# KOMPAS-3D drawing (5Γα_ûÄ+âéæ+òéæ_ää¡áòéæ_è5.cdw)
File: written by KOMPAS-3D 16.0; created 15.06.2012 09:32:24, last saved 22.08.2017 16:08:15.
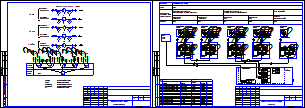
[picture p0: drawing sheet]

Sheets 1-2: A3, landscape

Title block, sheet 1: name: г. Москва, ул. Нежинская, д. 14, к.8 (кв. 1 и кв. 2); sheet number: 1; sheets: 27 / 28; sheet format: A3; stored path: D:\Проекты\Лыткарино\ул. Квартал 3А, д.25\710.74 РП.cdw; cell 320: Р
Title block, sheet 2: sheet number: 2

Views: Вид 2, Вид 3, Вид 4, Вид 5
Referenced files in C:\Program Files (x86)\ASCON\KOMPAS-3D V16\Sys\: SPDS.lcs, EngSys.lcs, GRAPHIC.LHS
Referenced files: graphic.tdp
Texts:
  МО, Клинский район, д. Решетниково, ул. Центральная, д.14
  GOST Common
  Normal
  List Paragraph
  heading 3
  для схемы
  txt
  краны
  Фоновая заливка
  Т0-элементы
  Агрегат
  Системный блок  МКТС
  Среда
  Вода
  параметра и место
  отбора импульса
  Учет тепловой энергии и
  теплоносителя системы отопления
  Подающий
  трубопровод
  отопления
  Обратный
  расхода горячей водысистемы ГВС
  Вводной
  трубопровод ХВС
  Узел учета ХВС
  ГВС
  ИМ1
  ИМ2
  ИМ3
  ИМ4
  ИМ5
  ВРУ
  Плата подключений
  СБ МКТС
  Pt 100
  Преобразователь
  температуры
  давления
  Измерительный
  модуль М121
  UP+
  UP-
  ИМП
  Лин
  каб.
  Начало
  трассы
  Трассы
  Марка
  Проложен
  Датчик температуры (Т1)
  Датчик температуры (Т2)
  Датчик температуры (Т3)
  Датчик температуры (Т4)
  Датчик давления (Т1)
  Датчик давления (Т2)
  Датчик давления (Т3)
  Датчик давления (В1)
  Датчик давления (Т4)
  Изм. модуль (Т1)
  Изм. модуль (Т2)
  Изм. модуль (Т3)
  Изм. модуль (Т4)
  Изм. модуль (В1)
  ВРУ 220В, 50 Гц
  ИМ1 УУТЭ
  ИМ2 УУТЭ
  ИМ2 УУГВС
  ИМ1 УУХВС
  ИМ (Т1)
  ИМ (Т3)
  FTP
  ПВС
  Конец
  Кол-во и
  сеч. жил
  Длина,
  приборы
  по месту
  шкаф
  учета
  UQIES
  Преобразователь расхода
  Термопреобразователь
  Преобразователь давления
  Преобразователь цифровой
  Системный блок МКТС
  Функциональная схема
  УУГВС
  УУТЭ
  УУХВС
  Размеры, параметризация
  сит. план
  подача ГВС
  обратка ГВС
  хвс
  обратка
  POLYLINE_STYLE_0.25_RGB_0_0_0
  стены
  Основная (не является границей для штриховки)
  POLYLINE_STYLE_0.18_RGB_0_0_0
  ХВС
  зеленая
  Красная тонкая
  арматура
  Подача
  Скрытая линия
  Ось Z
  Ось Y
  Ось X
  Образующая трубопровода (проектируемого)
  Трубопровод толщиной 0.6мм (одна линия)
  Трубопровод толщиной 1.2мм (одна линия)
  Трубопровод толщиной 1.0мм (одна линия)
  Трубопровод толщиной 0.8мм (одна линия)
  Трубопровод существующий (одна линия)
  Трубопровод невидимый (одна линия)
  Трубопровод демонтируемый (одна линия)
  Осевая трубопровода
  Осевая трубопровода (демонтируемого)
  Образующая трубопровода (существующего)
  Образующая трубопровода (невидимого)
  Изолированный трубопровод проектируемый (одна линия)
  Изолированный трубопровод существующий (одна линия)
  Образующая изоляции
  Изоляция
  Изолированный трубопровод невидимый (одна линия)
  Штрих пвс 075
  штрих пвс 2,5
  существующее оборудование
  Существующее оборудование
  K5LT_BASIC_RGB_0_0_255_THICK_0.53
  POLYLINE_STYLE_1.51_RGB_0_0_255
  POLYLINE_STYLE_0.50_RGB_128_128_128
  K5LT_AXLED_RGB_255_128_0_SC_1_THICK_0.18
  ACAD_ISO04W100_RGB_0_0_0_SC_1_THICK_0.18
  тонкая черная
  пломбировка
  Провода
  синий штрих
  Стили документа
  G2co
  расход вторичной воды объемный
  расход вторичной воды объемный при 70гр
  Gco
  расход теплоносителя массовый
  расход теплоносит объемн подающ
  расход теплоносит объемн обр
  Лапир
  Ghvs
  Im1
  Im2
  Im3
  Im4
  Im5
  Khvs
  норматив ХВС
  число подъездов
  число этажей
  Nkv
  число квартир
  тепловая нагрузка на отопление
  сумма Q
  Qgvs
  тепловая нагрузка ГВС
  тепловая нагрузка на циркуляцию ГВС
  иммитовставка или под манометр
  ro1
  ro2
  ro3
  ro4
  верх предел темп граф
  нижн предел темп граф
  темп подачи ГВС
  темп обр ГВС
  темр хол воды
  vzdh
  Kchn
  Ktp
  Knp
  beta
  tnv
  Vклап
  KLP
  RPD
  RDS
  PUMP
  ro5
  Переход К-76 x 3-38 x 2-09Г2С ГОСТ 17378-2001
  Переход ГОСТ 17378-2001
  Переход
  ГОСТ
  Сталь 09Г2С ГОСТ 19281-89
  Переход К-76 x 3-45 x 2,5-09Г2С ГОСТ 17378-2001
  Переход К-57 x 3-38 x 2-09Г2С ГОСТ 17378-2001
  Переход К-57 x 3-32 x 2-09Г2С ГОСТ 17378-2001
  Втулка 20x50
  Переход К-108 x 4-57 x 3-09Г2С ГОСТ 17378-2001
  Переход К-45 x 2,5-32 x 2-09Г2С ГОСТ 17378-2001
  Переход К-89 x 3,5-45 x 2,5-09Г2С ГОСТ 17378-2001
  Переход К-133 x 5-108 x 4-09Г2С ГОСТ 17378-2001
  Переход К-159 x 4,5-89 x 3,5-09Г2С ГОСТ 17378-2001
  Переход К-45 x 2,5-38 x 2-09Г2С ГОСТ 17378-2001
  Фланец 1-32-1 Ст3сп ГОСТ 12820-80
  Фланцы
  Фланец
  квадратный
  Ст3сп
  Ст3сп ГОСТ 380-2005
  Переход К-57 x 3-45 x 2,5-09Г2С ГОСТ 17378-2001
  Переход К-76 x 3-57 x 3-09Г2С ГОСТ 17378-2001
  Фланец 1-50-16 Ст3сп ГОСТ 12821-80
  Переход К-89 x 3,5-76 x 3,5-09Г2С ГОСТ 17378-2001
  Переход К-108 x 4-89 x 3,5-09Г2С ГОСТ 17378-2001
  Тройник 159 x 4,5-09Г2С ГОСТ 17376-2001
  Тройники ГОСТ 17376-2001
  Тройник
  Отвод 90-159 x 4-09Г2С ГОСТ 17375-2001
  Отвод ГОСТ 17375-2001
  Отвод
  Переход К-108 x 4-76 x 3,5-09Г2С ГОСТ 17378-2001
  Переход К-159 x 4,5-108 x 4-09Г2С ГОСТ 17378-2001
  Переход К-133 x 5-76 x 3,5-09Г2С ГОСТ 17378-2001
  Переход К-133 x 4-89 x 3,5-09Г2С ГОСТ 17378-2001
  Переход К-1-42,4 x 2,6-21,3 x 2-TS10 ГОСТ 17378-2001
  TS10
  Сталь TS10 ИСО 2604/2-75
  Фланец 1-20-16 Ст3сп ГОСТ 12820-80
  Лит-Масса-Масштаб
  Материал-Предприятие
  Title Specification
  Body Specification ( left align )
  Body Specificaton ( centered )
  Поз.
  Кол.
  Приме-
  чание
  Таблица спецификации
  Засыпка
  Штрих3
  Штрих2
  Штрих1
  Песок
  Штр0.5пр7
  Штр0.5пр12
  Штр0.3пр10
  Штр1.4пр21.21
  Штр1пр15
  Штр2.12пр35
  Штр1.5пр25
  Штр2.82пр42.42
  Штр2пр30
  SACNCR_ISO 1
  Электрощитовая
  Пр-1
  Ок-1
  вапвыапвы
  Обозначение стандарта
  Типоразмер
  Разраб.
  Пров.
  Т.контр.
  Н.контр.
  Утв.
  автоматизации
  Рабочие чертежи основного комплекта. ГОСТ Р 21.1101-2009 Ф3
  Стадия
  Лист
  Листов
  Изм.
  Кол.уч.
  №док.
  Подп.
  Дата
  Изменение
  Номер документа
  Подпись
  Наименование объекта строительства, в состав которого входит здание, наим. микр
  Наименование здания (сооружения)
  Порядковый номер листа
  Количество листов в документе
  Наименование изображения
  Индекс предприятия, выпускающего документ
  Инв. № подл.
  Подп. и дата
  Взам. инв. №
  Инвентарный номер подлинника
  Подпись принявшего подлинник на хранение
  Инвентарный номер подлинника, взамен которого выпущен данный подлинник
  Согласовано
  Формат листа
  Согласование
  03 Рабочие чертежи основного комплекта. ГОСТ Р 21.1101-2009 Ф3
  Схема соединений внешних
  проводок
Dimensions and other numbers on the sheet: 0; 220В; 50Гц; 1; 2; 3; 6; 5; 4; 4-20; 2x2x0,52; 3х0,75; 15; 25; 11; 16; 20; 10; 7; 17; 60; 4,0; 2,6582; 0,0160; 95; 2,6160; 3,0; 0,7862; 0,0060; 70; 9; 12; 13; 14; 8; 18; 0,4088; 50; 1,2,3,4,5; 6,7,8,9; 10,11,12,13,14; 15,16,17,18,19; 19; 0,0; 0,0000; 09Г2С; 21; 22; 23; 24; 26; 30; 31; 33; 34; 52; 64; 65; 66; 67; 69; 71; 72; 73; 74; 75; 27; 28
